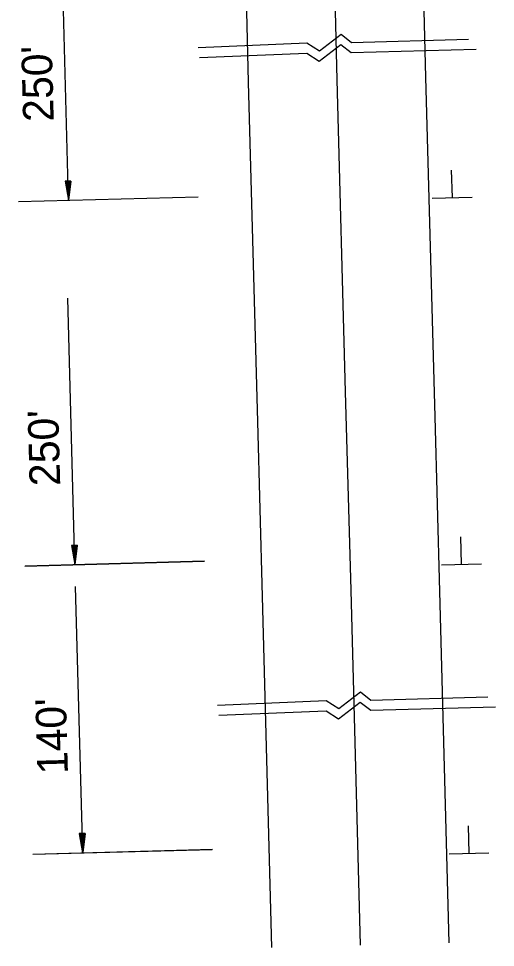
# Model space of a CAD drawing. Extents: x 1929624 to 1935547, y 596315 to 605721.
# Drawn here: x 1930906.1 to 1930999.5, y 596317.2 to 596499.2 of the extents above; entities that cross this region are included whole.
import ezdxf

# ---------------------------------------------------------------- set-up
doc = ezdxf.new("R2010")
doc.units = 0
doc.layers.add('Default', color=7, linetype='Continuous')

msp = doc.modelspace()

# ---------------------------------------------------------------- linework, layer by layer
at = {"layer": 'Default'}
for p, q in [((1930951.15, 596486.74), (1930949.3, 596555.72)), ((1930968.53, 596487.21), (1930966.68, 596556.19)), ((1930985.91, 596487.68), (1930984.06, 596556.66)), ((1930915.84, 596463.58), (1930914.44, 596515.75)), ((1930952.94, 596420.15), (1930951.15, 596486.74)), ((1930970.17, 596426.06), (1930968.53, 596487.21)), ((1930987.69, 596421.14), (1930985.91, 596487.68)), ((1930991.08, 596464.13), (1930990.94, 596469.47)), ((1930916.3, 596467.35), (1930915.18, 596467.32)), ((1930915.18, 596467.32), (1930915.84, 596463.58)), ((1930915.27, 596467.32), (1930915.82, 596464.21)), ((1930915.37, 596467.32), (1930915.81, 596464.85)), ((1930915.46, 596467.32), (1930915.79, 596465.48)), ((1930915.56, 596467.33), (1930915.77, 596466.11)), ((1930915.65, 596467.33), (1930915.76, 596466.74)), ((1930915.83, 596467.33), (1930915.76, 596466.74)), ((1930915.92, 596467.34), (1930915.77, 596466.11)), ((1930916.02, 596467.34), (1930915.79, 596465.48)), ((1930916.11, 596467.34), (1930915.81, 596464.85)), ((1930916.21, 596467.34), (1930915.82, 596464.21)), ((1930916.3, 596467.35), (1930915.84, 596463.58)), ((1930906.05, 596463.32), (1930941.25, 596464.26)), ((1930994.97, 596464.12), (1930987.15, 596463.91)), ((1930917.11, 596392.2), (1930915.71, 596444.37)), ((1930971.22, 596387.14), (1930970.17, 596426.06)), ((1930988.61, 596386.9), (1930987.69, 596421.14)), ((1930953.86, 596385.91), (1930952.94, 596420.15)), ((1930992.89, 596392.28), (1930992.75, 596397.62)), ((1930917.55, 596395.93), (1930916.43, 596395.9)), ((1930916.43, 596395.9), (1930917.09, 596392.17)), ((1930917.57, 596395.97), (1930916.45, 596395.94)), ((1930916.45, 596395.94), (1930917.11, 596392.2)), ((1930916.52, 596395.9), (1930917.08, 596392.79)), ((1930916.54, 596395.94), (1930917.09, 596392.83)), ((1930916.62, 596395.91), (1930917.06, 596393.44)), ((1930916.64, 596395.94), (1930917.08, 596393.48)), ((1930916.71, 596395.91), (1930917.04, 596394.06)), ((1930916.73, 596395.95), (1930917.06, 596394.1)), ((1930916.81, 596395.91), (1930917.02, 596394.7)), ((1930916.83, 596395.95), (1930917.04, 596394.73)), ((1930916.9, 596395.91), (1930917.01, 596395.32)), ((1930916.92, 596395.95), (1930917.03, 596395.36)), ((1930917.08, 596395.92), (1930917.01, 596395.32)), ((1930917.17, 596395.92), (1930917.02, 596394.7)), ((1930917.1, 596395.96), (1930917.03, 596395.36)), ((1930917.19, 596395.96), (1930917.04, 596394.73)), ((1930917.27, 596395.92), (1930917.04, 596394.06)), ((1930917.29, 596395.96), (1930917.06, 596394.1)), ((1930917.36, 596395.93), (1930917.06, 596393.44)), ((1930917.38, 596395.96), (1930917.08, 596393.48)), ((1930917.46, 596395.93), (1930917.08, 596392.79)), ((1930917.48, 596395.97), (1930917.09, 596392.83)), ((1930917.55, 596395.93), (1930917.09, 596392.17)), ((1930917.57, 596395.97), (1930917.11, 596392.2)), ((1930907.3, 596391.9), (1930942.5, 596392.85)), ((1930907.32, 596391.94), (1930942.52, 596392.89)), ((1930996.79, 596392.27), (1930988.97, 596392.06)), ((1930918.63, 596335.73), (1930917.23, 596387.9)), ((1930973.08, 596317.63), (1930971.22, 596387.14)), ((1930990.46, 596318.09), (1930988.61, 596386.9)), ((1930955.7, 596317.16), (1930953.86, 596385.91)), ((1930994.37, 596335.66), (1930994.23, 596341)), ((1930919.07, 596339.45), (1930917.95, 596339.42)), ((1930917.95, 596339.42), (1930918.61, 596335.69)), ((1930919.09, 596339.49), (1930917.96, 596339.46)), ((1930917.96, 596339.46), (1930918.63, 596335.73)), ((1930918.04, 596339.42), (1930918.59, 596336.31)), ((1930918.06, 596339.46), (1930918.61, 596336.35)), ((1930918.13, 596339.43), (1930918.57, 596336.96)), ((1930918.15, 596339.47), (1930918.59, 596337)), ((1930918.23, 596339.43), (1930918.56, 596337.58)), ((1930918.25, 596339.47), (1930918.58, 596337.62)), ((1930918.32, 596339.43), (1930918.54, 596338.22)), ((1930918.34, 596339.47), (1930918.56, 596338.26)), ((1930918.42, 596339.44), (1930918.52, 596338.85)), ((1930918.44, 596339.47), (1930918.54, 596338.88)), ((1930918.6, 596339.44), (1930918.52, 596338.85)), ((1930918.61, 596339.48), (1930918.54, 596338.88)), ((1930918.69, 596339.44), (1930918.54, 596338.22)), ((1930918.71, 596339.48), (1930918.56, 596338.26)), ((1930918.79, 596339.45), (1930918.56, 596337.58)), ((1930918.88, 596339.45), (1930918.57, 596336.96)), ((1930918.81, 596339.48), (1930918.58, 596337.62)), ((1930918.9, 596339.49), (1930918.59, 596337)), ((1930918.98, 596339.45), (1930918.59, 596336.31)), ((1930918.99, 596339.49), (1930918.61, 596336.35)), ((1930919.07, 596339.45), (1930918.61, 596335.69)), ((1930919.09, 596339.49), (1930918.63, 596335.73)), ((1930908.82, 596335.43), (1930944.02, 596336.37)), ((1930908.84, 596335.46), (1930944.04, 596336.41)), ((1930998.26, 596335.65), (1930990.44, 596335.44))]:
    msp.add_line(p, q, dxfattribs=at)
for points in [[(1930941.28, 596493.52), (1930962.57, 596494.42), (1930965.03, 596492.86), (1930969.27, 596496.14), (1930971.31, 596494.53), (1930994.27, 596495.14)], [(1930941.52, 596491.53), (1930962.54, 596492.42), (1930965, 596490.86), (1930969.24, 596494.14), (1930971.28, 596492.53), (1930995.73, 596493.18)], [(1930945.07, 596364.64), (1930966.36, 596365.53), (1930968.82, 596363.97), (1930973.06, 596367.25), (1930975.11, 596365.64), (1930998.07, 596366.25)], [(1930945.32, 596362.65), (1930966.33, 596363.53), (1930968.79, 596361.97), (1930973.03, 596365.25), (1930975.08, 596363.64), (1930999.53, 596364.29)]]:
    msp.add_lwpolyline(points, dxfattribs=at)

# ---------------------------------------------------------------- texts
for s, p in [("250'", (1930912.96, 596479.04)), ("250'", (1930914.23, 596407.66)), ("140'", (1930915.74, 596351.18))]:
    msp.add_text(s, height=6, rotation=91.5377, dxfattribs=at).set_placement(p)

doc.saveas('drawing.dxf')
